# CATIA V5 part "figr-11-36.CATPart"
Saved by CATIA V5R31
Part number: Part1
Bounding box of the stored display mesh (mm): x -55 to 66, y -170 to 170, z -50 to 0
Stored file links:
  D:\PROJECTS\Project 2021\US EDITION\CATIA V5 6R 2021\Resources\Part Files\c11_catia_v5_6r2021_prt\figr-11-36.CATPart
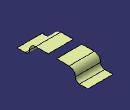
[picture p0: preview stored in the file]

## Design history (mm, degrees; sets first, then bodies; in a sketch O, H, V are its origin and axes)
Set1
  Extrude1: Element1 Sketch1, Lim1 66, Lim2 55, Direction yz-plane
  Symmetry1: ToTransfor Extrude1, Reference zx-plane
Body1 (main body)
  Sketch1 on yz-plane, origin (0, 0, 0), H (0, 1, 0), V (0, 0, 1)
    point P1 (20, 0)
    line L1 (20, 0) -> (80, 0)
    arc A1 centre (80, -30) radius 30 from (80, 0) to (110, -30) cw
    arc A2 centre (130, -30) radius 20 from (110, -30) to (130, -50) ccw
    line L2 (130, -50) -> (170, -50)
    coincidence: P1 H
    horizontal: L1 H
    tangency: A1 L1, A2 A1, L2 A2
